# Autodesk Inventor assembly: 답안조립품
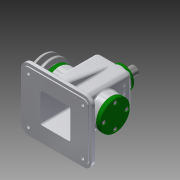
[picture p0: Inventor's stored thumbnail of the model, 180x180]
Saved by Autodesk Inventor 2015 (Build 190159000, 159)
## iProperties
Created: 2016-02
Part Number: 답안조립품
Document SubType Name: Assembly
Designer: Administrator
Author: Administrator
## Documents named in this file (19)
- C:\Users\Administrator\Desktop\460219V1016\답안조립품.iam
- C:\Users\Administrator\Desktop\460219V1016\V-벨트풀리.ipt
- C:\Users\Administrator\Desktop\460219V1016\고정핀.ipt
- C:\Users\Administrator\Desktop\460219V1016\뒤커버.ipt
- C:\Users\Administrator\Desktop\460219V1016\링크.ipt
- C:\Users\Administrator\Desktop\460219V1016\멈춤링 6 x 5.ipt
- C:\Users\Administrator\Desktop\460219V1016\멈춤링 15 x 1.ipt
- C:\Users\Administrator\Desktop\460219V1016\베어링 15 x 35 x 11.ipt
- C:\Users\Administrator\Desktop\460219V1016\본체.ipt
- C:\Users\Administrator\Desktop\460219V1016\볼트 M3 x 8.ipt
- C:\Users\Administrator\Desktop\460219V1016\볼트 M4 x 10.ipt
- C:\Users\Administrator\Desktop\460219V1016\볼트 M6 x 12.ipt
- C:\Users\Administrator\Desktop\460219V1016\상부부시.ipt
- C:\Users\Administrator\Desktop\460219V1016\슬라이드바.ipt
- C:\Users\Administrator\Desktop\460219V1016\앞커버.ipt
- C:\Users\Administrator\Desktop\460219V1016\오일실 15 25 7.ipt
- C:\Users\Administrator\Desktop\460219V1016\와셔.ipt
- C:\Users\Administrator\Desktop\460219V1016\키 5 x 5 x 14.ipt
- C:\Users\Administrator\Desktop\460219V1016\편심축.ipt
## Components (15 placed, 5 different names)
1. V-벨트풀리:1
2. 고정핀:1
3. ISO 4018 M6 x 12:1
4. ISO 4762 M4 x 10:2
5. ISO 4762 M4 x 10:3
6. ISO 4762 M4 x 10:4
7. ISO 4762 M4 x 10:5
8. ISO 4762 M4 x 10:1
9. ISO 4762 M4 x 10:6
10. ISO 4762 M4 x 10:7
11. ISO 4762 M4 x 10:8
12. ISO 4762 M3 x 8:1
13. ISO 4762 M3 x 8:2
14. ISO 4762 M3 x 8:3
15. ISO 4762 M3 x 8:4
